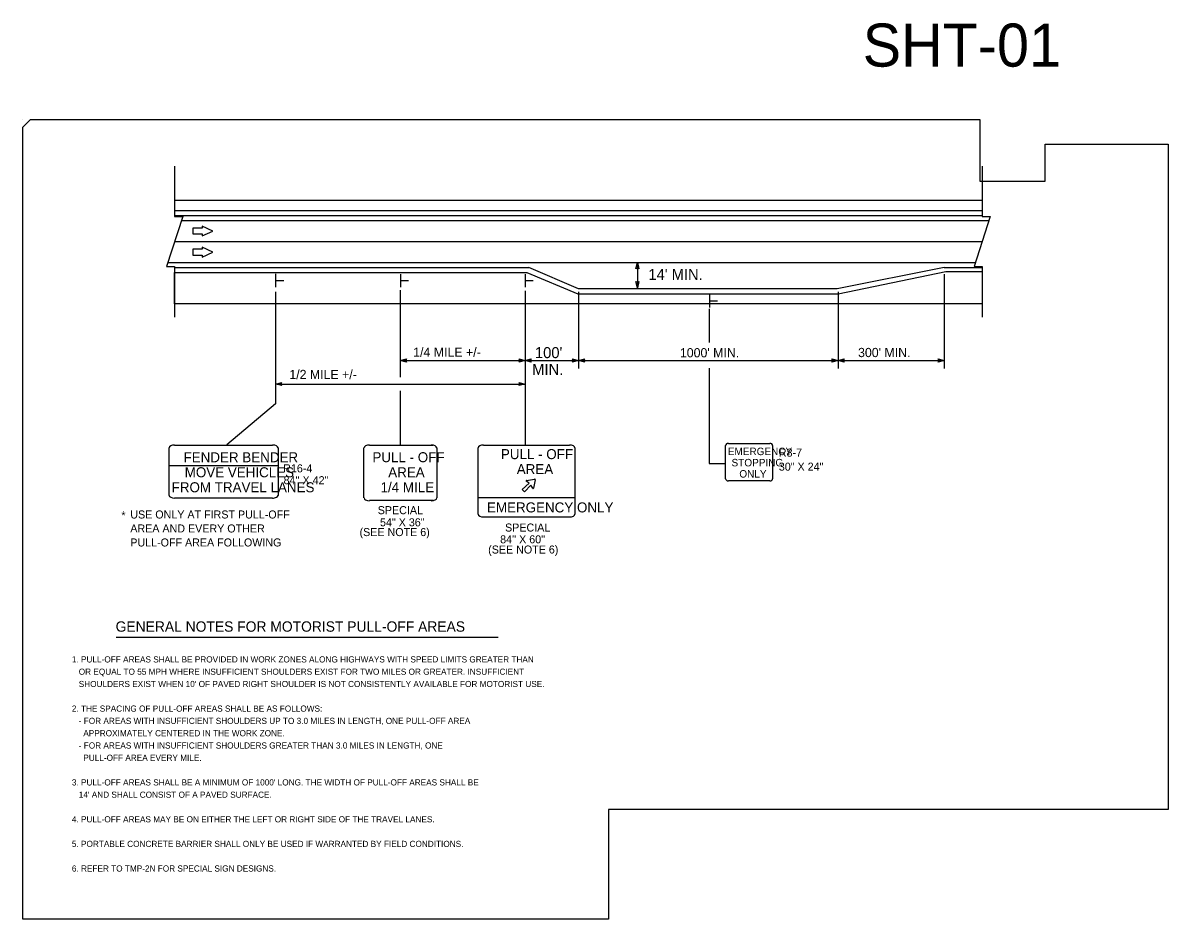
# Model space of a CAD drawing. Extents: x 2487017 to 2488507, y 370218 to 371384.
import ezdxf

# ---------------------------------------------------------------- set-up
doc = ezdxf.new("R2010")
doc.units = 0
for name, color, linetype in [('RS R11-3 CELL', 7, 'Continuous'), ('RS R11-4 CELL', 7, 'Continuous'), ('RS R8-3 CELL', 7, 'Continuous'), ('Scratch_Level_3', 7, 'Continuous'), ('TC CONSTRUCTION PROPOSED ROADWAY SHADE', 7, 'Continuous'), ('TC DEV BARRIER PCB (UN-ANCHORED)', 7, 'Continuous'), ('TC DEV SIGN', 7, 'Continuous'), ('TC LABEL DIMENSION', 7, 'Continuous'), ('TC LABEL DIRECTION OF TRAFFIC FLOW ARROW', 7, 'Continuous'), ('TC LABEL TEXT', 7, 'Continuous'), ('TC PM EDGELINE 4 W PA', 7, 'Continuous'), ('TC PM EDGELINE 4 Y PB', 7, 'Continuous'), ('TC PM SKIP 4 W PC', 7, 'Continuous'), ('TC SHEET LAYOUT SHAPE', 7, 'Continuous'), ('Text', 7, 'Continuous')]:
    doc.layers.add(name, color=color, linetype=linetype)

msp = doc.modelspace()

# ---------------------------------------------------------------- linework, layer by layer
at = {"layer": 'RS R11-3 CELL'}
for points in [[(2487214, 370834.8), (2487267.9, 370834.8)], [(2487267.9, 370834.8), (2487341.4, 370834.8)], [(2487467.5, 370834.8), (2487521.4, 370834.8)], [(2487521.4, 370834.8), (2487550.3, 370834.8)], [(2487616, 370834.8), (2487669.9, 370834.8)], [(2487669.9, 370834.8), (2487727.7, 370834.8)], [(2487206.9, 370769.5), (2487206.9, 370831.3)], [(2487348.5, 370831.3), (2487348.5, 370769.5)], [(2487460.3, 370766.1), (2487460.3, 370831.3)], [(2487555, 370831.3), (2487555, 370766.1)], [(2487608.9, 370744.9), (2487608.9, 370831.3)], [(2487734.8, 370831.3), (2487734.8, 370744.9)], [(2487206.9, 370808.4), (2487348.5, 370808.4)], [(2487267.9, 370766), (2487214, 370766)], [(2487341.4, 370766), (2487267.9, 370766)], [(2487521.4, 370762.6), (2487467.5, 370762.6)], [(2487550.3, 370762.6), (2487521.4, 370762.6)], [(2487608.9, 370766.5), (2487734.8, 370766.5)], [(2487669.9, 370741.3), (2487616, 370741.3)], [(2487727.7, 370741.3), (2487669.9, 370741.3)]]:
    msp.add_lwpolyline(points, dxfattribs=at)
for centre, major_axis, start_param, end_param in [((2487214, 370831.3), (-7.12, 0), 4.712162, 6.283185), ((2487341.4, 370831.3), (7.12, 0), 0, 1.570796), ((2487467.5, 370831.3), (-7.12, 0), 4.712162, 6.283185), ((2487547.9, 370831.3), (7.12, 0), 0, 1.570796), ((2487616, 370831.3), (-7.12, 0), 4.712162, 6.283185), ((2487727.7, 370831.3), (7.12, 0), 0, 1.570796), ((2487214, 370769.5), (-7.12, 0), 0, 1.570796), ((2487341.4, 370769.5), (-7.12, 0), 1.570796, 3.141593), ((2487467.5, 370766.1), (-7.12, 0), 0, 1.570796), ((2487547.9, 370766.1), (-7.12, 0), 1.570796, 3.141593), ((2487616, 370744.9), (-7.12, 0), 0, 1.570796), ((2487727.7, 370744.9), (-7.12, 0), 1.570796, 3.141593)]:
    msp.add_ellipse(centre, major_axis=major_axis, ratio=0.5, start_param=start_param, end_param=end_param, dxfattribs=at)
at = {"layer": 'RS R8-3 CELL'}
msp.add_line((2487991.9, 370834.3), (2487991.9, 370791.1), dxfattribs=at)
for points in [[(2487930.9, 370791.1), (2487930.9, 370834.3)], [(2487934.4, 370837.1), (2487988.4, 370837.1)], [(2487988.4, 370788.3), (2487934.4, 370788.3)]]:
    msp.add_lwpolyline(points, dxfattribs=at)
for centre, major_axis, start_param, end_param in [((2487934.4, 370834.3), (-3.56, 0), 4.712389, 6.283185), ((2487988.4, 370834.3), (3.56, 0), 0, 1.570796), ((2487934.4, 370791.1), (-3.56, 0), 6.282958, 7.853982), ((2487988.4, 370791.1), (-3.56, 0), 1.570796, 3.141593)]:
    msp.add_ellipse(centre, major_axis=major_axis, ratio=0.8, start_param=start_param, end_param=end_param, dxfattribs=at)
at = {"layer": 'Scratch_Level_3'}
msp.add_line((2487016.6, 371258.3), (2487016.6, 371258.3), dxfattribs=at)
at = {"layer": 'TC CONSTRUCTION PROPOSED ROADWAY SHADE'}
for p, q in [((2487214, 371152.9), (2487214, 371139.9)), ((2487214, 371018.8), (2487214, 371031.8))]:
    msp.add_line(p, q, dxfattribs=at)
for points in [[(2488264.6, 371152.9), (2487214, 371152.9)], [(2487214, 371139.9), (2488264.6, 371139.9)], [(2487214, 371031.8), (2487214, 371059.2), (2487672.1, 371059.2), (2487738.7, 371031.8), (2487868, 371031.8), (2488077.1, 371031.8), (2488217.5, 371060.8), (2488264.6, 371060.8)], [(2488264.6, 371060.8), (2488264.6, 371018.8)], [(2488264.6, 371018.8), (2487214, 371018.8)]]:
    msp.add_lwpolyline(points, dxfattribs=at)
at = {"layer": 'TC DEV BARRIER PCB (UN-ANCHORED)'}
for points in [[(2487214, 371133.4), (2488264.6, 371133.4)], [(2487214, 371065.7), (2487674.9, 371065.7)], [(2487739.3, 371038.3), (2487674.9, 371065.7)], [(2488215.4, 371065.7), (2488076.1, 371038.3)], [(2488215.4, 371065.7), (2488264.6, 371065.7)], [(2488076.1, 371038.3), (2487739.3, 371038.3)]]:
    msp.add_lwpolyline(points, dxfattribs=at)
at = {"layer": 'TC DEV SIGN'}
for p, q in [((2487345.3, 371057.5), (2487345.3, 371040.5)), ((2487507.7, 371057.4), (2487507.7, 371040.4)), ((2487670.1, 371057.4), (2487670.1, 371040.4)), ((2487345.3, 371049), (2487355.9, 371049)), ((2487507.7, 371048.9), (2487518.2, 371048.9)), ((2487670.1, 371048.9), (2487680.6, 371048.9)), ((2487909.8, 371031), (2487909.8, 371014)), ((2487909.8, 371022.5), (2487920.3, 371022.5))]:
    msp.add_line(p, q, dxfattribs=at)
at = {"layer": 'TC LABEL DIMENSION'}
for p, q in [((2487675.2, 370785.2), (2487671.4, 370787.8)), ((2487671.6, 370788.9), (2487682.3, 370790.6)), ((2487683.1, 370789.7), (2487681, 370779)), ((2487666, 370777.2), (2487675.2, 370785.2)), ((2487669.1, 370774), (2487666, 370777.2)), ((2487677.4, 370782.6), (2487669.1, 370774)), ((2487679.9, 370778.7), (2487677.4, 370782.6))]:
    msp.add_line(p, q, dxfattribs=at)
for centre, radius, start, end in [((2487671.7, 370788.3), 0.567, 100.1103, 242.3866), ((2487682.4, 370789.9), 0.736, 351.8267, 94.1644), ((2487680.4, 370779.1), 0.62, 224.0551, 347.6619)]:
    msp.add_arc(centre, radius, start, end, dxfattribs=at)
at = {"layer": 'TC LABEL DIRECTION OF TRAFFIC FLOW ARROW'}
for p, q in [((2487250, 371117), (2487237.5, 371117)), ((2487237.5, 371117), (2487237.5, 371109.5)), ((2487263.5, 371113.2), (2487250, 371119.6)), ((2487250, 371119.6), (2487250, 371117)), ((2487237.5, 371109.5), (2487250, 371109.5)), ((2487250, 371106.9), (2487263.5, 371113.2)), ((2487250, 371109.5), (2487250, 371106.9)), ((2487250, 371089.7), (2487237.5, 371089.7)), ((2487237.5, 371089.7), (2487237.5, 371082.1)), ((2487263.5, 371085.9), (2487250, 371092.2)), ((2487250, 371092.2), (2487250, 371089.7)), ((2487250, 371079.5), (2487263.5, 371085.9)), ((2487237.5, 371082.1), (2487250, 371082.1)), ((2487250, 371082.1), (2487250, 371079.5))]:
    msp.add_line(p, q, dxfattribs=at)
at = {"layer": 'TC LABEL TEXT'}
for p, q in [((2487816, 371072.2), (2487816, 371039.6)), ((2488215.4, 371057.1), (2488215.4, 370934.6)), ((2487739.3, 371034.1), (2487739.3, 370934.6)), ((2488077.1, 371034.1), (2488077.1, 370934.6)), ((2487507.5, 370944.9), (2487739.3, 370944.9)), ((2487739.3, 370944.9), (2488079.9, 370944.9)), ((2488079.9, 370944.9), (2488215.4, 370944.9)), ((2487347.4, 370914.3), (2487669.9, 370914.3)), ((2487137.8, 370585.2), (2487634.8, 370585.2))]:
    msp.add_line(p, q, dxfattribs=at)
for points in [[(2487813.9, 371064.1), (2487816, 371072.2), (2487818, 371064.1)], [(2487813.9, 371064.1), (2487816, 371072.2), (2487818, 371064.1)], [(2487818, 371047.8), (2487816, 371039.6), (2487813.9, 371047.8)], [(2487818, 371047.8), (2487816, 371039.6), (2487813.9, 371047.8)], [(2487345.2, 371034.3), (2487345.2, 370888.4), (2487281.8, 370835.2)], [(2487507.5, 371036.6), (2487507.5, 370923.3)], [(2487669.9, 371035.5), (2487669.9, 370834.8)], [(2487909.6, 371012.3), (2487909.6, 370968.5)], [(2487515.7, 370942.9), (2487507.5, 370944.9), (2487515.7, 370947)], [(2487515.7, 370942.9), (2487507.5, 370944.9), (2487515.7, 370947)], [(2487661.8, 370947), (2487669.9, 370944.9), (2487661.8, 370942.9)], [(2487661.8, 370947), (2487669.9, 370944.9), (2487661.8, 370942.9)], [(2487678, 370942.9), (2487669.9, 370944.9), (2487678, 370947)], [(2487678, 370942.9), (2487669.9, 370944.9), (2487678, 370947)], [(2487731.2, 370947), (2487739.3, 370944.9), (2487731.2, 370942.9)], [(2487731.2, 370947), (2487739.3, 370944.9), (2487731.2, 370942.9)], [(2487747.5, 370942.9), (2487739.3, 370944.9), (2487747.5, 370947)], [(2487747.5, 370942.9), (2487739.3, 370944.9), (2487747.5, 370947)], [(2488068.9, 370947), (2488077.1, 370944.9), (2488068.9, 370942.9)], [(2488068.9, 370947), (2488077.1, 370944.9), (2488068.9, 370942.9)], [(2488085.2, 370942.9), (2488077.1, 370944.9), (2488085.2, 370947)], [(2488085.2, 370942.9), (2488077.1, 370944.9), (2488085.2, 370947)], [(2488207.2, 370947), (2488215.4, 370944.9), (2488207.2, 370942.9)], [(2488207.2, 370947), (2488215.4, 370944.9), (2488207.2, 370942.9)], [(2487909.6, 370934.9), (2487909.6, 370810.8), (2487930.9, 370810.8)], [(2487353.3, 370912.3), (2487345.2, 370914.3), (2487353.3, 370916.4)], [(2487353.3, 370912.3), (2487345.2, 370914.3), (2487353.3, 370916.4)], [(2487661.8, 370916.4), (2487669.9, 370914.3), (2487661.8, 370912.3)], [(2487661.8, 370916.4), (2487669.9, 370914.3), (2487661.8, 370912.3)]]:
    msp.add_lwpolyline(points, dxfattribs=at)
for centre, start, end in [((2487816, 371062.3), 41.3264, 138.6736), ((2487816, 371062.3), 41.3264, 138.6736), ((2487816, 371049.6), 221.3264, 318.6736), ((2487816, 371049.6), 221.3264, 318.6736), ((2487517.5, 370944.9), 131.3264, 228.6736), ((2487517.5, 370944.9), 131.3264, 228.6736), ((2487660, 370944.9), 311.3264, 48.6736), ((2487660, 370944.9), 311.3264, 48.6736), ((2487679.8, 370944.9), 131.3264, 228.6736), ((2487679.8, 370944.9), 131.3264, 228.6736), ((2487729.4, 370944.9), 311.3264, 48.6736), ((2487729.4, 370944.9), 311.3264, 48.6736), ((2487749.3, 370944.9), 131.3264, 228.6736), ((2487749.3, 370944.9), 131.3264, 228.6736), ((2488067.1, 370944.9), 311.3264, 48.6736), ((2488067.1, 370944.9), 311.3264, 48.6736), ((2488087, 370944.9), 131.3264, 228.6736), ((2488087, 370944.9), 131.3264, 228.6736), ((2488205.4, 370944.9), 311.3264, 48.6736), ((2488205.4, 370944.9), 311.3264, 48.6736), ((2487355.1, 370914.3), 131.3264, 228.6736), ((2487355.1, 370914.3), 131.3264, 228.6736), ((2487660, 370914.3), 311.3264, 48.6736), ((2487660, 370914.3), 311.3264, 48.6736)]:
    msp.add_arc(centre, 2.71, start, end, dxfattribs=at)
at = {"layer": 'TC PM EDGELINE 4 W PA'}
msp.add_line((2487205.3, 371072.2), (2488255.9, 371072.2), dxfattribs=at)
at = {"layer": 'TC PM EDGELINE 4 Y PB'}
msp.add_line((2487222.8, 371126.9), (2488273.4, 371126.9), dxfattribs=at)
at = {"layer": 'TC PM SKIP 4 W PC'}
msp.add_line((2487214, 371099.5), (2488264.6, 371099.5), dxfattribs=at)
at = {"layer": 'TC SHEET LAYOUT SHAPE'}
msp.add_lwpolyline([(2487016.6, 370666.8), (2487016.6, 370976.2), (2487016.6, 371248.3), (2487026.6, 371258.3), (2487469.6, 371258.3), (2487940.6, 371258.3), (2488261.6, 371258.3), (2488261.6, 371178.3), (2488346.6, 371178.3), (2488346.6, 371226.3), (2488506.6, 371226.3), (2488506.6, 370891.3), (2488506.6, 370612.1), (2488506.6, 370360.8), (2487778.4, 370360.8), (2487778.4, 370218.3), (2487608.9, 370218.3), (2487256.1, 370218.3), (2487016.6, 370218.3)], close=True, dxfattribs=at)
at = {"layer": 'Text'}
for points in [[(2487214, 371197.9), (2487214, 371132.1), (2487224.5, 371132.1), (2487203.6, 371067), (2487214, 371067), (2487214, 371001.1)], [(2487214, 371197.9), (2487214, 371132.1), (2487224.5, 371132.1), (2487203.6, 371067), (2487214, 371067), (2487214, 371001.1)], [(2488264.6, 371197.9), (2488264.6, 371132.1), (2488275, 371132.1), (2488254.2, 371067), (2488264.6, 371067), (2488264.6, 371001.1)], [(2487214, 371132.1), (2487224.5, 371132.1)], [(2487507.5, 370905.4), (2487507.5, 370834.8)]]:
    msp.add_lwpolyline(points, dxfattribs=at)

# ---------------------------------------------------------------- texts
at = {"layer": 'RS R11-3 CELL'}
for s, height, p in [('FENDER BENDER', 13.021, (2487225.6, 370812.5)), ('PULL - OFF', 13.02, (2487471.3, 370812.6)), ('PULL - OFF', 13.02, (2487638.5, 370816.6)), ('MOVE VEHICLES', 13.021, (2487227.1, 370793)), ('AREA', 13.02, (2487491.9, 370793)), ('AREA', 13.02, (2487659.1, 370797.1)), ("84'' X 42''", 10.417, (2487355.7, 370784)), ('FROM TRAVEL LANES', 13.021, (2487210.1, 370773.5)), ('1/4 MILE', 13.02, (2487481.9, 370773.5)), ('EMERGENCY ONLY', 13.021, (2487620.4, 370747.3)), ("84'' X 60''", 10.417, (2487637.5, 370707.1))]:
    msp.add_text(s, height=height, dxfattribs=at).set_placement(p)
at = {"layer": 'RS R11-4 CELL'}
for s, height, p in [('R8-7', 10.42, (2488000.1, 370819.9)), ('R16-4', 10.42, (2487355.2, 370799.4)), ('30" X 24"', 10.42, (2488000.1, 370801.6)), ('SPECIAL', 10.42, (2487478.2, 370745)), ('54" X 36"', 10.42, (2487481.2, 370729.2)), ('SPECIAL', 10.42, (2487643.9, 370722.4)), ('(SEE NOTE 6)', 10.417, (2487454.6, 370716.5)), ('(SEE NOTE 6)', 10.417, (2487621.9, 370693.8))]:
    msp.add_text(s, height=height, dxfattribs=at).set_placement(p)
at = {"layer": 'RS R8-3 CELL'}
for s, p in [('EMERGENCY', (2487933.7, 370821.8)), ('STOPPING', (2487938.6, 370807.2)), ('ONLY', (2487948.7, 370792.6))]:
    msp.add_text(s, height=9.72, dxfattribs=at).set_placement(p)
at = {"layer": 'TC LABEL TEXT'}
for s, height, p in [("14' MIN.", 14.32, (2487830.4, 371049.7)), ('1/4 MILE +/-', 12, (2487524.4, 370949.7)), ("100'", 14.32, (2487682.8, 370948)), ("1000' MIN.", 12, (2487871.4, 370949)), ("300' MIN.", 12, (2488103.2, 370949.3)), ('MIN.', 14.32, (2487679.2, 370926.2)), ('1/2 MILE +/-', 12, (2487363.2, 370920.7)), ('GENERAL NOTES FOR MOTORIST PULL-OFF AREAS', 13.477, (2487137.2, 370592.1)), ('1. PULL-OFF AREAS SHALL BE PROVIDED IN WORK ZONES ALONG HIGHWAYS WITH SPEED LIMITS GREATER THAN', 8, (2487080.3, 370552.1)), ('   OR EQUAL TO 55 MPH WHERE INSUFFICIENT SHOULDERS EXIST FOR TWO MILES OR GREATER. INSUFFICIENT', 8, (2487080.3, 370536.1)), ("   SHOULDERS EXIST WHEN 10' OF PAVED RIGHT SHOULDER IS NOT CONSISTENTLY AVAILABLE FOR MOTORIST USE. ", 8, (2487080.3, 370520.1)), ('2. THE SPACING OF PULL-OFF AREAS SHALL BE AS FOLLOWS:', 8, (2487080.3, 370488.1)), ('   - FOR AREAS WITH INSUFFICIENT SHOULDERS UP TO 3.0 MILES IN LENGTH, ONE PULL-OFF AREA ', 8, (2487080.3, 370472.1)), ('     APPROXIMATELY CENTERED IN THE WORK ZONE.', 8, (2487080.3, 370456.1)), ('   - FOR AREAS WITH INSUFFICIENT SHOULDERS GREATER THAN 3.0 MILES IN LENGTH, ONE ', 8, (2487080.3, 370440.1)), ('     PULL-OFF AREA EVERY MILE.', 8, (2487080.3, 370424.1)), ("3. PULL-OFF AREAS SHALL BE A MINIMUM OF 1000' LONG. THE WIDTH OF PULL-OFF AREAS SHALL BE", 8, (2487080.3, 370392.1)), ("   14' AND SHALL CONSIST OF A PAVED SURFACE.", 8, (2487080.3, 370376.1)), ('4. PULL-OFF AREAS MAY BE ON EITHER THE LEFT OR RIGHT SIDE OF THE TRAVEL LANES. ', 8, (2487080.3, 370344.1)), ('5. PORTABLE CONCRETE BARRIER SHALL ONLY BE USED IF WARRANTED BY FIELD CONDITIONS.', 8, (2487080.3, 370312.1)), ('6. REFER TO TMP-2N FOR SPECIAL SIGN DESIGNS.', 8, (2487080.3, 370280.1))]:
    msp.add_text(s, height=height, dxfattribs=at).set_placement(p)
at = {"layer": 'TC SHEET LAYOUT SHAPE'}
msp.add_text('SHT-01', height=56, rotation=0.0001, dxfattribs=at).set_placement((2488109.2, 371327.2))
at = {"layer": 'Text'}
for s, height, p in [('*', 10.4, (2487144.7, 370738.2)), ('USE ONLY AT FIRST PULL-OFF', 10.417, (2487156.3, 370739.4)), ('AREA AND EVERY OTHER', 10.417, (2487156.3, 370721.2)), ('PULL-OFF AREA FOLLOWING', 10.417, (2487156.3, 370703))]:
    msp.add_text(s, height=height, dxfattribs=at).set_placement(p)

doc.saveas('drawing.dxf')
